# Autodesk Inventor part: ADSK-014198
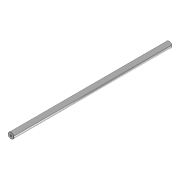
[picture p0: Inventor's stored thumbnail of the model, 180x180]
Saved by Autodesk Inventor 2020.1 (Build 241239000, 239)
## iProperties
Created: 1999-11
Part Number: ADSK-014198
Description: SHFTTA,RC,AX,340,12,EE,SHAFT,VERTICAL
Document SubType Name: Modeling
Designer: sspink
Material: Générique
Density: 1 g/cm^3
Appearance: Chrom - poliert
Mass: 682.189 g
Surface Area: 895.198 cm^2
Volume: 682.189 cm^3
Control State: 0
Checked Out: False
Master: False
Shininess: 0.0
Length Units: 11269
Angle Units: 11279
Time Units: 11290
Mass Units: 11283
Length Display Precision: 3
Angle Display Precision: 2
Compacted: True
Dimensions: 32x32x855 mm
Mass: 0,682 kg
DocNumber: ADSK-014198
Folder: 01 - Themengebiete\Simplification\01 - Packaging machine\
Original: C:\AB_Vault\CAD\01 - Themengebiete\Simplification\01 - Packaging machine\Parts\ADSK-011300.ipt
VDS_Category: 3D Komponenten
VDS_NumSchm: Autodesk
Density: 0.0
Volumn: 0.0
Area: 0.0
PropertySet Name: Model Information
Author: sspink
Revision Number: -
Title: SHFTTA,RC,AX,340,12,EE,SHAFT,VERTICAL
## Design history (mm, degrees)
node "Hole2" dims "d9" = 10.106, "d10" = 9.525, "d11" = 6.35, "d12" = 60 deg, "d13" = 32.3, "d14" = 118 deg, "d19" = 24
node "Chamfer1" dims "d15" = 1, "d16" = 1, "d17" = 45 deg
node "Solide1"
  node "Extrusion1" dims "d1" = 855, "d2" = 0
  node "Hole1" dims "d3" = 10.106, "d4" = 9.525, "d5" = 6.35, "d6" = 60 deg, "d7" = 32.3, "d8" = 118 deg, "d18" = 24
sketch "Sketch1"
  geometry: C1 r 16 at (0, 0)
  constraints: 1 centre point, 1 other
  dimensions: "d0" = 32 diameter of C1
node "Corps solides"
node "Corps surfaciques"
sketch "Sketch2"
  geometry: C1 r 16 at (0, 0) reference; 1 further point
  constraints: 1 coincident
sketch "Sketch4"
  geometry: C1 r 16 at (0, 0) reference; 1 further point
  constraints: 1 coincident
